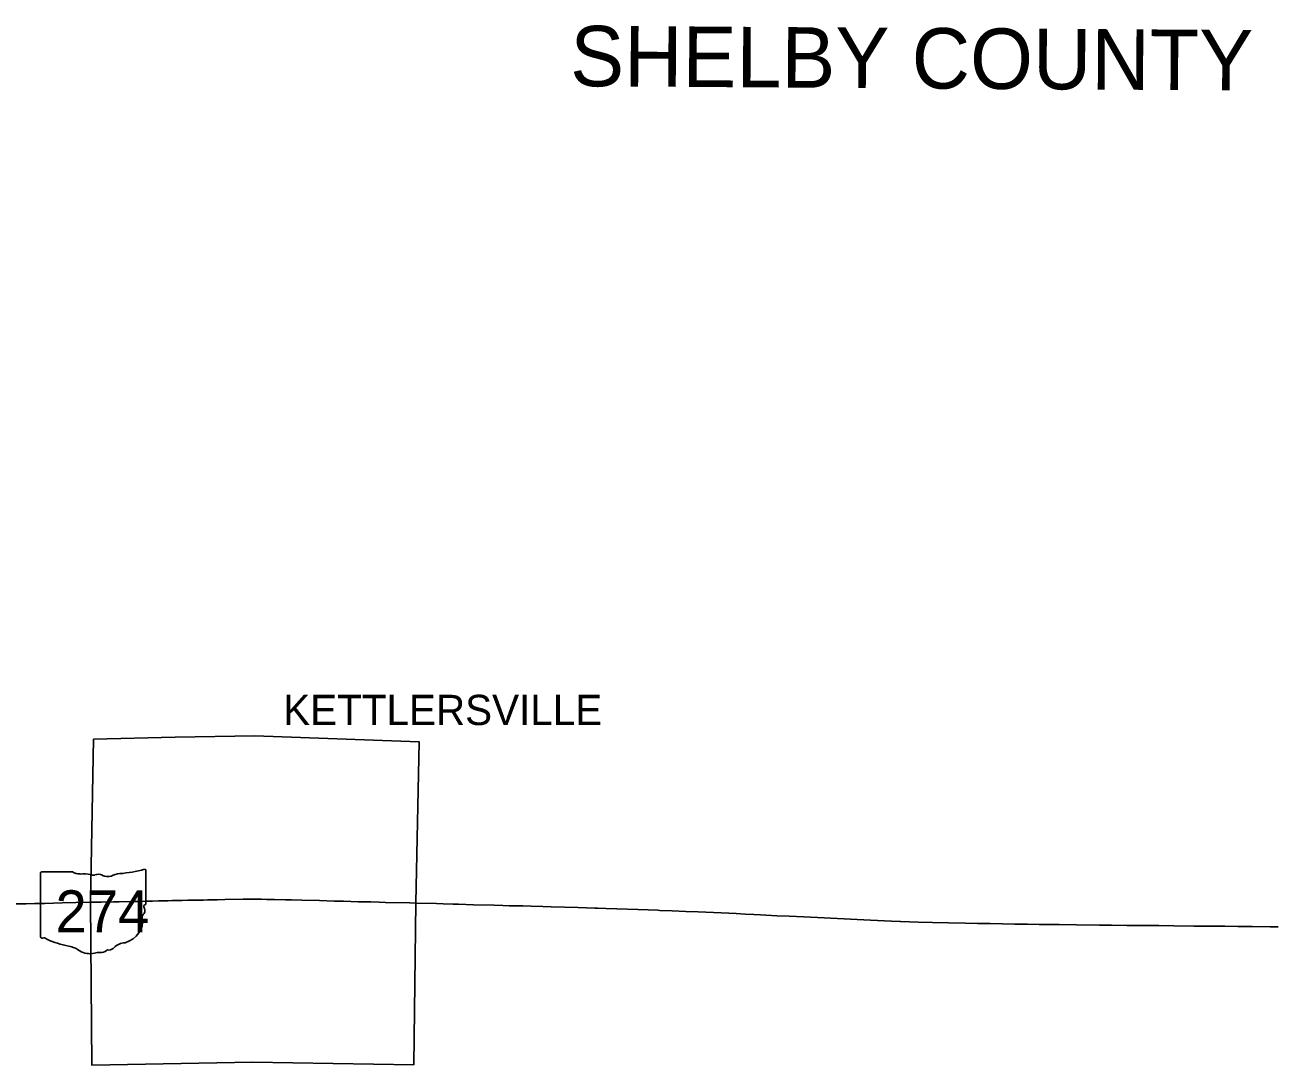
# Model space of a CAD drawing. Extents: x 0 to 34, y 0 to 22.
# Drawn here: x 5.0101 to 5.3415, y 19.1084 to 19.3849 of the extents above; entities that cross this region are included whole.
import ezdxf

# ---------------------------------------------------------------- set-up
doc = ezdxf.new("R2010")
doc.units = 0
for name, color, linetype in [('GM_X_Corporation', 7, 'Continuous'), ('GM_X_Corporation_Text', 7, 'Continuous'), ('GM_X_County_Text', 7, 'Continuous'), ('GM_X_State_Location', 7, 'Continuous'), ('GM_X_State_Route', 7, 'Continuous'), ('GM_X_State_Shield', 7, 'Continuous')]:
    doc.layers.add(name, color=color, linetype=linetype)

msp = doc.modelspace()

# ---------------------------------------------------------------- linework, layer by layer
at = {"layer": 'GM_X_Corporation'}
msp.add_lwpolyline([(5.11355, 19.10845), (5.07061, 19.10916), (5.02789, 19.10838), (5.02754, 19.15169), (5.02836, 19.19502), (5.05004, 19.19554), (5.07128, 19.19588), (5.11493, 19.19434), (5.11408, 19.15147)], close=True, dxfattribs=at)
at = {"layer": 'GM_X_State_Route'}
for points in [[(5.00598, 19.15118), (5.00721, 19.15121), (5.01043, 19.15126), (5.01269, 19.1513), (5.01544, 19.15138), (5.02002, 19.15147), (5.02366, 19.15156), (5.02756, 19.15165)], [(5.02756, 19.15165), (5.03042, 19.15171), (5.03369, 19.15175), (5.03481, 19.15178), (5.03517, 19.15179), (5.0387, 19.15184), (5.04002, 19.15188), (5.04206, 19.15194)], [(5.04206, 19.15194), (5.04223, 19.15195), (5.04402, 19.15198), (5.04566, 19.15201), (5.0464, 19.15203)], [(5.0464, 19.15203), (5.04808, 19.15208), (5.04928, 19.15211), (5.04951, 19.15211), (5.05098, 19.15214), (5.05193, 19.15216), (5.05341, 19.1522), (5.05531, 19.15222), (5.05763, 19.15226), (5.05863, 19.15229), (5.05905, 19.1523), (5.06063, 19.15232), (5.06126, 19.15233), (5.06327, 19.15238), (5.06817, 19.15248), (5.06943, 19.15249), (5.07087, 19.15248), (5.07138, 19.15248), (5.07164, 19.15248)], [(5.07164, 19.15248), (5.07302, 19.15246), (5.07444, 19.15244), (5.0765, 19.1524), (5.07945, 19.15234), (5.08103, 19.15228), (5.08372, 19.15221), (5.08841, 19.1521), (5.09247, 19.15197), (5.09484, 19.15192), (5.09875, 19.15182), (5.10212, 19.15175), (5.10433, 19.15168), (5.10597, 19.15162), (5.11245, 19.15148), (5.1141, 19.15142)], [(5.1141, 19.15142), (5.11957, 19.1513), (5.12136, 19.15124), (5.12399, 19.15117), (5.12542, 19.15112), (5.12937, 19.151), (5.13491, 19.15086), (5.13723, 19.15081), (5.13892, 19.15076), (5.14097, 19.15071), (5.1425, 19.15068), (5.14477, 19.15061), (5.14783, 19.15053), (5.15009, 19.15048), (5.15727, 19.15027), (5.16164, 19.15014), (5.16244, 19.15011)], [(5.16244, 19.15011), (5.16459, 19.15003), (5.16749, 19.14992), (5.17308, 19.14973), (5.17582, 19.14963), (5.17839, 19.14953)], [(5.17839, 19.14953), (5.17893, 19.14951), (5.1822, 19.14939), (5.18589, 19.14921), (5.18916, 19.1491), (5.19732, 19.14874), (5.19927, 19.14864), (5.20164, 19.14851), (5.20391, 19.14839), (5.20575, 19.14831), (5.21002, 19.14809), (5.21334, 19.14795), (5.21719, 19.14775), (5.22267, 19.14749), (5.235, 19.14693), (5.24053, 19.14664), (5.2428, 19.14654), (5.24306, 19.14653)], [(5.24306, 19.14653), (5.24767, 19.14639), (5.25146, 19.14631), (5.25571, 19.14621), (5.26025, 19.14612), (5.2634, 19.14605), (5.26679, 19.14599), (5.27333, 19.14586), (5.27667, 19.1458), (5.27978, 19.14578), (5.28289, 19.14573), (5.2851, 19.14571), (5.28969, 19.14565), (5.29581, 19.14559), (5.29908, 19.14557), (5.30314, 19.14552), (5.31163, 19.14546), (5.31564, 19.14542), (5.32096, 19.14535), (5.32808, 19.14528), (5.32917, 19.14527), (5.33267, 19.14523), (5.33641, 19.14518), (5.34121, 19.14516), (5.34338, 19.14517)]]:
    msp.add_lwpolyline(points, dxfattribs=at)
at = {"layer": 'GM_X_State_Shield'}
for p, q in [((5.01429, 19.15943), (5.01429, 19.14245)), ((5.02276, 19.15973), (5.01457, 19.15973)), ((5.04226, 19.15126), (5.04226, 19.16015)), ((5.04226, 19.15127), (5.04226, 19.15126))]:
    msp.add_line(p, q, dxfattribs=at)
for centre, major_axis, start_param, end_param in [((5.01461, 19.15947), (0.000324, 0), 1.712693, 3.28349), ((5.02471, 19.1617), (0.00314, 0), 4.042523, 4.731795), ((5.02575, 19.15019), (0.01128, 0), 1.404758, 1.657858), ((5.02831, 19.15956), (0.000907, 0), 3.836095, 5.185415), ((5.02964, 19.1576), (0.00189, 0), 0.950623, 2.079405), ((5.03208, 19.16029), (0.00227, 0), 4.081561, 5.145723), ((5.03608, 19.15454), (0.00597, 0), 1.699011, 2.107814), ((5.0323, 19.18288), (0.02966, 0), 4.814394, 5.042369), ((5.04195, 19.16018), (0.000311, 0), 6.141152, 7.989035), ((5.04338, 19.14754), (0.0021, 0), 2.387724, 3.262537), ((5.04219, 19.15061), (0.000482, 0), 1.883978, 3.671073), ((5.03913, 19.14949), (0.00289, 0), 5.934695, 6.695948), ((5.04193, 19.15123), (0.000333, 0), 5.05454, 6.418171), ((5.03396, 19.14641), (0.00742, 0), 5.101752, 6.440018), ((5.01461, 19.14241), (0.000327, 0), 3.00124, 4.508301), ((5.01466, 19.14415), (0.00249, 0), 4.665946, 4.897461), ((5.01517, 19.14147), (0.0009, 0), 0.519207, 1.627899), ((5.02653, 19.15673), (0.02142, 0), 4.195997, 4.488961), ((5.02015, 19.13482), (0.0067, 0), 0.823519, 1.323587), ((5.02739, 19.14139), (0.00425, 0), 4.026481, 4.996735), ((5.03016, 19.14011), (0.00227, 0), 4.691044, 5.507374), ((5.03221, 19.13847), (0.000638, 0), 1.147584, 2.315152), ((5.03194, 19.1408), (0.0024, 0), 4.937069, 5.64225), ((5.03709, 19.13768), (0.00406, 0), 1.647645, 2.488434), ((5.02985, 19.13551), (0.00349, 0), 1.495662, 1.94098)]:
    msp.add_ellipse(centre, major_axis=major_axis, ratio=0.8, start_param=start_param, end_param=end_param, dxfattribs=at)

# ---------------------------------------------------------------- texts
at = {"layer": 'GM_X_Corporation_Text'}
msp.add_text('KETTLERSVILLE', height=0.008037, rotation=0, dxfattribs=at).set_placement((5.0788, 19.19878))
at = {"layer": 'GM_X_County_Text'}
msp.add_text('SHELBY COUNTY', height=0.016074, rotation=359.6289, dxfattribs=at).set_placement((5.15507, 19.36865))
at = {"layer": 'GM_X_State_Location'}
msp.add_text('274', height=0.0000161, rotation=0, dxfattribs=at).set_placement((5.02229, 19.14864))
for s in ['s', 'r']:
    msp.add_text(s, height=0.0000161, dxfattribs=at).set_placement((5.02796, 19.14981))
at = {"layer": 'GM_X_State_Shield'}
msp.add_text('274', height=0.011189, dxfattribs=at).set_placement((5.01824, 19.14365))

doc.saveas('drawing.dxf')
